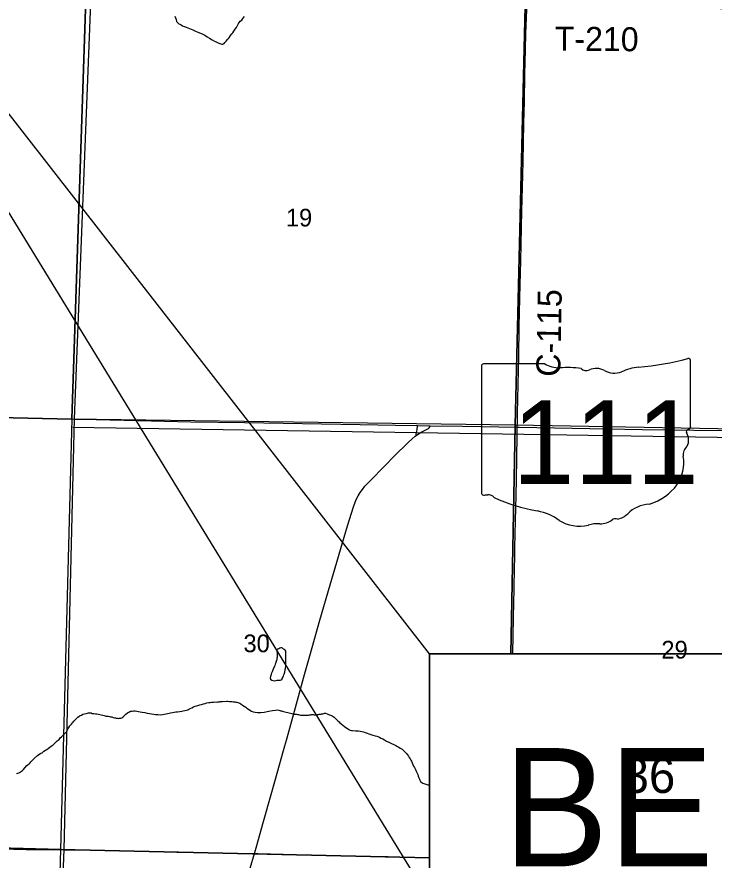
# Model space of a CAD drawing. Extents: x 2.4 to 73.1, y 4.5 to 25.6.
# Drawn here: x 30.38 to 31.205, y 19.109 to 20.107 of the extents above; entities that cross this region are included whole.
import ezdxf

# ---------------------------------------------------------------- set-up
doc = ezdxf.new("R2010")
doc.units = 0
for name, color, linetype in [('GM_X_County_Road', 7, 'Continuous'), ('GM_X_County_Road_Text', 7, 'Continuous'), ('GM_X_Interchange_Ramps', 7, 'Continuous'), ('GM_X_Minor_Lake', 7, 'Continuous'), ('GM_X_Minor_River', 7, 'Continuous'), ('GM_X_Section', 7, 'Continuous'), ('GM_X_Section_Text', 7, 'Continuous'), ('GM_X_State_Location', 7, 'Continuous'), ('GM_X_State_Route', 7, 'Continuous'), ('GM_X_State_Shield', 7, 'Continuous'), ('GM_X_Township', 7, 'Continuous'), ('GM_X_Township_Road', 7, 'Continuous'), ('GM_X_Township_Road_Text', 7, 'Continuous'), ('SH_Text', 7, 'Continuous')]:
    doc.layers.add(name, color=color, linetype=linetype)

msp = doc.modelspace()

# ---------------------------------------------------------------- linework, layer by layer
at = {"layer": 'GM_X_County_Road'}
for points in [[(30.97184, 19.62114), (30.972, 19.6277), (30.97223, 19.63767), (30.97251, 19.65477), (30.97354, 19.70449), (30.97424, 19.74024), (30.9753, 19.78996), (30.9759, 19.81793), (30.97738, 19.87698), (30.97806, 19.90495), (30.97877, 19.93447), (30.97975, 19.98109), (30.98037, 20.00595), (30.98101, 20.03858), (30.98161, 20.06811), (30.982, 20.08676), (30.98299, 20.11472), (30.98303, 20.11613)], [(30.8523, 19.61114), (30.85241, 19.61306), (30.85267, 19.61477), (30.85302, 19.61636), (30.85334, 19.61789), (30.85355, 19.61945), (30.85367, 19.6214), (30.85378, 19.62303)], [(30.8523, 19.61114), (30.85495, 19.61301), (30.85897, 19.61543), (30.8645, 19.61832), (30.86697, 19.61957), (30.86739, 19.61993), (30.86774, 19.62045), (30.86821, 19.6216), (30.8687, 19.6228)], [(30.8687, 19.6228), (30.90718, 19.62221), (30.97184, 19.62114)], [(30.66079, 19.11661), (30.66353, 19.12625), (30.67062, 19.1517), (30.68123, 19.18907), (30.68755, 19.21151), (30.69513, 19.23844), (30.69938, 19.25338), (30.71072, 19.29377), (30.72015, 19.32824), (30.72643, 19.3507), (30.73819, 19.39259), (30.7503, 19.43439), (30.77095, 19.50445), (30.77796, 19.52669), (30.77949, 19.53112), (30.7813, 19.53545), (30.78345, 19.53963), (30.78589, 19.54363), (30.78858, 19.54747), (30.79155, 19.5511), (30.79683, 19.55683), (30.81537, 19.57566), (30.82626, 19.58676), (30.84288, 19.60311), (30.84749, 19.60733), (30.85112, 19.61029), (30.8523, 19.61114)], [(30.53426, 18.61669), (30.53823, 18.63398), (30.54275, 18.65366), (30.55594, 18.71123), (30.56416, 18.74761), (30.57122, 18.77783), (30.57467, 18.79297), (30.58178, 18.82482), (30.58938, 18.85816), (30.59633, 18.88686), (30.60225, 18.90941), (30.60874, 18.93342), (30.61552, 18.95734), (30.62147, 18.97827), (30.64194, 19.05), (30.65591, 19.09934), (30.66079, 19.11661)]]:
    msp.add_lwpolyline(points, dxfattribs=at)
at = {"layer": 'GM_X_Interchange_Ramps'}
msp.add_lwpolyline([(30.41612, 18.61875), (30.43582, 19.1212), (30.44784, 19.63098), (30.47252, 20.25413), (30.47626, 20.50995), (30.48376, 20.60471), (30.48414, 20.61558), (30.49896, 21.13416), (30.49917, 21.1385), (30.51254, 21.51156)], dxfattribs=at)
at = {"layer": 'GM_X_Minor_Lake'}
for points in [[(30.68733, 19.35758), (30.68765, 19.3512), (30.68763, 19.35025), (30.6876, 19.34893), (30.68738, 19.3476), (30.68717, 19.34666), (30.68714, 19.34552), (30.68674, 19.34458), (30.68653, 19.34363), (30.68632, 19.34269), (30.68591, 19.34156), (30.68551, 19.34062), (30.68491, 19.33911), (30.6845, 19.33817), (30.6841, 19.33704), (30.68351, 19.33611), (30.68291, 19.33479), (30.68229, 19.3329), (30.68169, 19.33159), (30.68129, 19.33065), (30.68069, 19.32914), (30.68048, 19.3282), (30.68007, 19.32707), (30.67966, 19.32594), (30.67962, 19.32404), (30.67997, 19.32289), (30.68147, 19.32191), (30.68298, 19.3213), (30.68487, 19.32107), (30.68659, 19.32141), (30.68774, 19.32158), (30.68926, 19.32173), (30.69021, 19.32171), (30.69116, 19.32169), (30.69232, 19.32223), (30.69347, 19.32278), (30.69368, 19.32372), (30.69467, 19.3256), (30.69527, 19.32653), (30.69549, 19.32786), (30.69608, 19.32898), (30.6963, 19.33012), (30.6967, 19.33125), (30.69692, 19.33219), (30.69713, 19.33333), (30.69734, 19.33427), (30.69756, 19.33541), (30.69777, 19.33635), (30.69781, 19.33787), (30.69784, 19.33939), (30.69786, 19.34034), (30.6979, 19.34186), (30.69796, 19.3447), (30.69798, 19.34565), (30.698, 19.3466), (30.69803, 19.34774), (30.69806, 19.34907), (30.6979, 19.35021), (30.69812, 19.35154), (30.69814, 19.35249), (30.69798, 19.35382), (30.698, 19.35477), (30.69783, 19.35591), (30.6973, 19.35725), (30.69617, 19.35804), (30.69523, 19.35844), (30.69411, 19.35941), (30.69317, 19.35982), (30.69204, 19.36003), (30.69088, 19.35949), (30.68954, 19.35895), (30.68838, 19.35821), (30.68742, 19.35767), (30.68733, 19.35758)], [(30.68733, 19.35758), (30.68765, 19.3512), (30.68763, 19.35025), (30.6876, 19.34893), (30.68738, 19.3476), (30.68717, 19.34666), (30.68714, 19.34552), (30.68674, 19.34458), (30.68653, 19.34363), (30.68632, 19.34269), (30.68591, 19.34156), (30.68551, 19.34062), (30.68491, 19.33911), (30.6845, 19.33817), (30.6841, 19.33704), (30.68351, 19.33611), (30.68291, 19.33479), (30.68229, 19.3329), (30.68169, 19.33159), (30.68129, 19.33065), (30.68069, 19.32914), (30.68048, 19.3282), (30.68007, 19.32707), (30.67966, 19.32594), (30.67962, 19.32404), (30.67997, 19.32289), (30.68147, 19.32191), (30.68298, 19.3213), (30.68487, 19.32107), (30.68659, 19.32141), (30.68774, 19.32158), (30.68926, 19.32173), (30.69021, 19.32171), (30.69116, 19.32169), (30.69232, 19.32223), (30.69347, 19.32278), (30.69368, 19.32372)], [(30.69368, 19.32372), (30.69467, 19.3256), (30.69527, 19.32653), (30.69549, 19.32786), (30.69608, 19.32898), (30.6963, 19.33012), (30.6967, 19.33125), (30.69692, 19.33219), (30.69713, 19.33333), (30.69734, 19.33427), (30.69756, 19.33541), (30.69777, 19.33635), (30.69781, 19.33787), (30.69784, 19.33939), (30.69786, 19.34034), (30.6979, 19.34186), (30.69796, 19.3447), (30.69798, 19.34565), (30.698, 19.3466), (30.69803, 19.34774), (30.69806, 19.34907), (30.6979, 19.35021), (30.69812, 19.35154), (30.69814, 19.35249), (30.69798, 19.35382), (30.698, 19.35477), (30.69783, 19.35591), (30.6973, 19.35725), (30.69617, 19.35804), (30.69523, 19.35844), (30.69411, 19.35941), (30.69317, 19.35982), (30.69204, 19.36003), (30.69088, 19.35949), (30.68954, 19.35895), (30.68838, 19.35821), (30.68742, 19.35767), (30.68733, 19.35758)]]:
    msp.add_lwpolyline(points, dxfattribs=at)
at = {"layer": 'GM_X_Minor_River'}
for points in [[(30.5668, 20.1074), (30.56732, 20.1053), (30.56804, 20.10338), (30.56874, 20.10109), (30.57023, 20.09953), (30.57134, 20.09837), (30.57247, 20.09777), (30.57397, 20.09698), (30.57566, 20.09599), (30.57755, 20.09519), (30.58, 20.09437), (30.58791, 20.09115), (30.59036, 20.09015), (30.59393, 20.08855), (30.59695, 20.08734), (30.59977, 20.08614), (30.60221, 20.08475), (30.60483, 20.08298), (30.60784, 20.0812), (30.61084, 20.07943), (30.61365, 20.07765), (30.61628, 20.07645), (30.61854, 20.07545), (30.62005, 20.07504), (30.621, 20.07464), (30.62213, 20.07442), (30.62346, 20.0742), (30.625, 20.07512), (30.62597, 20.07623), (30.62734, 20.07772), (30.6289, 20.07959), (30.63007, 20.08089)], [(30.63007, 20.08089), (30.63125, 20.08238), (30.63243, 20.08445), (30.634, 20.08631), (30.63517, 20.0878), (30.63654, 20.08967), (30.63793, 20.09192), (30.63949, 20.09397), (30.64069, 20.09641), (30.64207, 20.09885), (30.64384, 20.10128), (30.64577, 20.10276), (30.64715, 20.10463), (30.6491, 20.10705)], [(32.22285, 19.35283), (32.22507, 19.59303), (30.44608, 19.62066)], [(30.49208, 19.27815), (30.49359, 19.27773), (30.4951, 19.27732), (30.49643, 19.2771), (30.49737, 19.27689), (30.49851, 19.27667), (30.49964, 19.27645), (30.5006, 19.27662), (30.50174, 19.2766), (30.50289, 19.27695), (30.50404, 19.27731), (30.505, 19.27785), (30.50578, 19.27879), (30.50695, 19.28009), (30.5087, 19.28157), (30.51063, 19.28304), (30.51236, 19.28395), (30.51428, 19.28486), (30.51619, 19.2852), (30.51772, 19.28535), (30.51962, 19.28531), (30.52549, 19.28423), (30.52814, 19.28379), (30.53098, 19.28334), (30.53382, 19.28271), (30.53647, 19.28227), (30.53912, 19.28183), (30.54159, 19.28158), (30.54386, 19.28115), (30.5467, 19.2809), (30.54917, 19.28084), (30.55184, 19.28116), (30.55413, 19.28149), (30.55623, 19.28182), (30.55795, 19.28216), (30.55986, 19.28269), (30.56158, 19.28303), (30.56368, 19.28355), (30.56578, 19.28388), (30.56769, 19.28422), (30.56978, 19.28436), (30.57264, 19.28468), (30.57474, 19.28501), (30.57665, 19.28535), (30.57856, 19.28568), (30.58047, 19.28621), (30.582, 19.28656), (30.58335, 19.28729), (30.58489, 19.28801), (30.58662, 19.28911), (30.58854, 19.29002), (30.59085, 19.29091), (30.59372, 19.2918), (30.59621, 19.2925), (30.59831, 19.29302), (30.60061, 19.29373), (30.60271, 19.29425), (30.60462, 19.29478), (30.60673, 19.2953), (30.60863, 19.29545), (30.61015, 19.2956), (30.61129, 19.29558), (30.61244, 19.29574), (30.61377, 19.2959), (30.61548, 19.29586), (30.61701, 19.29602), (30.61834, 19.29618), (30.61948, 19.29615), (30.62044, 19.29632), (30.62158, 19.2963), (30.6231, 19.29645), (30.62824, 19.29671), (30.62938, 19.29669), (30.63128, 19.29665), (30.6328, 19.29642), (30.63432, 19.29639), (30.63602, 19.29616), (30.63754, 19.29593), (30.63886, 19.29571), (30.64, 19.2955), (30.64113, 19.29528), (30.64226, 19.29488), (30.6434, 19.29447), (30.6449, 19.29368), (30.64658, 19.29231), (30.64883, 19.29112), (30.65052, 19.28994), (30.65201, 19.28858), (30.65369, 19.28721), (30.65537, 19.28603), (30.65744, 19.28504), (30.65951, 19.28423), (30.66178, 19.2838), (30.66463, 19.28336), (30.66824, 19.28346), (30.67224, 19.28394), (30.67798, 19.28514), (30.68218, 19.286), (30.68561, 19.2863), (30.68808, 19.28643), (30.6896, 19.28621)], [(30.37934, 19.21119), (30.38068, 19.21154), (30.38183, 19.21189), (30.38299, 19.21263), (30.38395, 19.21317), (30.38511, 19.21391), (30.38627, 19.21483), (30.38743, 19.21594), (30.38919, 19.21818), (30.39134, 19.2206), (30.39328, 19.22227), (30.39482, 19.22299), (30.39541, 19.22393), (30.39639, 19.22505), (30.39737, 19.22635), (30.39833, 19.22709), (30.3995, 19.2282), (30.40009, 19.22914), (30.40397, 19.23266), (30.40551, 19.23358), (30.40648, 19.23431), (30.40821, 19.23522), (30.40956, 19.23576), (30.41169, 19.23761), (30.41362, 19.23871), (30.41535, 19.23981), (30.41709, 19.2411), (30.41883, 19.24239), (30.42038, 19.2435), (30.42135, 19.24442), (30.42231, 19.24497), (30.42348, 19.24589), (30.42503, 19.24757), (30.42639, 19.24868), (30.42756, 19.24979), (30.42872, 19.25071), (30.42969, 19.25164), (30.43106, 19.25332), (30.43261, 19.2548), (30.43398, 19.25629), (30.43533, 19.2574), (30.4365, 19.25851), (30.43748, 19.25963), (30.43844, 19.26037), (30.43885, 19.2615), (30.43926, 19.26263), (30.43985, 19.26375), (30.44044, 19.26469), (30.44123, 19.26581), (30.44241, 19.2675), (30.44319, 19.26843), (30.44417, 19.26973), (30.44534, 19.27123), (30.44632, 19.27216), (30.44729, 19.27327), (30.44885, 19.27495), (30.45196, 19.27791), (30.45332, 19.27902), (30.45467, 19.27994), (30.45601, 19.28048), (30.45793, 19.28139), (30.45985, 19.28191), (30.46157, 19.28244), (30.4631, 19.28279), (30.46443, 19.28295), (30.46539, 19.28312), (30.46653, 19.28309), (30.46747, 19.28288), (30.46879, 19.28247), (30.47069, 19.28224), (30.47258, 19.282), (30.47448, 19.28177), (30.47619, 19.28154), (30.47789, 19.28113), (30.4794, 19.28071), (30.48129, 19.28029), (30.48318, 19.27987), (30.48526, 19.27925), (30.48773, 19.279), (30.48924, 19.27878), (30.49056, 19.27837), (30.49208, 19.27815)], [(30.6896, 19.28621), (30.69073, 19.28599), (30.69167, 19.28559), (30.69281, 19.28538), (30.69394, 19.28497), (30.69527, 19.28475), (30.69678, 19.28434), (30.69829, 19.28392), (30.70037, 19.2835), (30.70207, 19.28289), (30.70358, 19.28266), (30.7049, 19.28225), (30.70623, 19.28204), (30.70736, 19.28163), (30.7085, 19.2816), (30.70964, 19.28139), (30.71059, 19.28137), (30.71172, 19.28115), (30.71305, 19.28093), (30.71551, 19.2805), (30.71722, 19.28046), (30.72273, 19.28033), (30.72464, 19.28048), (30.72616, 19.28063), (30.72749, 19.28079), (30.72845, 19.28096), (30.7294, 19.28094), (30.73035, 19.28092), (30.73149, 19.28089), (30.7332, 19.28085), (30.73434, 19.28083), (30.73548, 19.28099), (30.73663, 19.28116), (30.73758, 19.28132), (30.73854, 19.28149), (30.73968, 19.28166), (30.74063, 19.28183), (30.74178, 19.28199), (30.74292, 19.28215), (30.74388, 19.28251), (30.74502, 19.28249), (30.74691, 19.28206), (30.74861, 19.28127), (30.74974, 19.28086), (30.75087, 19.28045), (30.752, 19.28005), (30.75294, 19.27946), (30.75387, 19.27868), (30.75518, 19.27789), (30.75667, 19.27634), (30.75797, 19.27517), (30.75908, 19.27381), (30.76002, 19.27303), (30.76095, 19.27225), (30.76207, 19.27127), (30.76337, 19.27011), (30.76561, 19.26835), (30.76729, 19.26698), (30.76917, 19.2658), (30.77104, 19.26442), (30.77272, 19.26325), (30.77423, 19.26264), (30.77554, 19.26204), (30.77669, 19.26202), (30.7803, 19.26194), (30.78182, 19.2619), (30.78409, 19.26166), (30.7858, 19.26143), (30.78788, 19.261), (30.78977, 19.26058), (30.79204, 19.25996), (30.79411, 19.25896), (30.79637, 19.25815), (30.79863, 19.25734), (30.80109, 19.25672), (30.80354, 19.2559), (30.80562, 19.25529), (30.80864, 19.25427), (30.81052, 19.25328), (30.81258, 19.25228), (30.81465, 19.25109), (30.81709, 19.24971), (30.81972, 19.24832), (30.82292, 19.24692), (30.82574, 19.24552), (30.82818, 19.24433), (30.83006, 19.24334), (30.83175, 19.24254), (30.83344, 19.24136), (30.83569, 19.23998), (30.83755, 19.23823), (30.83922, 19.23667), (30.84071, 19.23493), (30.842, 19.23338), (30.8431, 19.23165), (30.84402, 19.23011), (30.84513, 19.22875), (30.84585, 19.22722), (30.84677, 19.22568), (30.8473, 19.22396), (30.84839, 19.22184)], [(30.84839, 19.22184), (30.84911, 19.22012), (30.85021, 19.21819), (30.8513, 19.21589), (30.8524, 19.21397), (30.8533, 19.21186), (30.85401, 19.20994), (30.85473, 19.20802), (30.85526, 19.20611), (30.85599, 19.20477), (30.85652, 19.20324), (30.85744, 19.2017), (30.85894, 19.20071), (30.86025, 19.19973), (30.86591, 19.1979), (30.86803, 19.19785)]]:
    msp.add_lwpolyline(points, dxfattribs=at)
at = {"layer": 'GM_X_Section'}
for points in [[(30.46142, 20.1284), (30.4449, 19.63056), (29.94145, 19.64208), (29.95885, 20.13725)], [(30.46148, 20.13105), (30.98121, 20.11878), (30.9693, 19.62349), (30.4449, 19.63056), (30.46142, 20.1284)], [(31.4812, 20.11358), (31.47128, 19.61446), (30.9693, 19.62349), (30.98121, 20.11878)], [(29.94145, 19.64208), (30.4449, 19.63056), (30.43117, 19.12128), (29.92965, 19.13465)], [(30.9642, 19.35283), (30.9693, 19.62349), (30.4449, 19.63056), (30.43117, 19.12128), (30.86803, 19.11145), (30.86803, 19.35283)], [(31.46656, 19.35283), (31.47128, 19.61446), (30.9693, 19.62349), (30.9642, 19.35283)], [(29.92965, 19.13465), (30.43117, 19.12128), (30.41719, 18.61809), (29.91527, 18.62994)], [(30.86803, 19.11145), (30.43117, 19.12128), (30.41719, 18.61809), (30.9167, 18.60894), (30.95137, 18.60852), (30.95403, 18.77027), (30.86803, 18.77027)]]:
    msp.add_lwpolyline(points, close=True, dxfattribs=at)
at = {"layer": 'GM_X_State_Route'}
for points in [[(30.19518, 19.63567), (30.22176, 19.63552), (30.24818, 19.63497), (30.28703, 19.63402), (30.31501, 19.63342), (30.39583, 19.63184), (30.43934, 19.6309), (30.44796, 19.6307)], [(30.44796, 19.6307), (30.47353, 19.63013), (30.52327, 19.62908), (30.58543, 19.62758), (30.64916, 19.62646), (30.78594, 19.62408), (30.82791, 19.62343), (30.85378, 19.62303), (30.8687, 19.6228)], [(30.8687, 19.6228), (30.90718, 19.62221), (30.97184, 19.62114)], [(30.97184, 19.62114), (30.97401, 19.62108), (31.01598, 19.62036), (31.12011, 19.6185), (31.18073, 19.61748), (31.21959, 19.61694)]]:
    msp.add_lwpolyline(points, dxfattribs=at)
at = {"layer": 'GM_X_State_Shield'}
for p, q in [((31.17681, 19.62127), (31.17681, 19.69978)), ((30.92962, 19.69348), (30.92962, 19.54339)), ((31.00444, 19.69607), (30.93205, 19.69607)), ((31.17678, 19.62129), (31.17681, 19.62127))]:
    msp.add_line(p, q, dxfattribs=at)
for centre, major_axis, start_param, end_param in [((30.93245, 19.6938), (0.00286, 0), 1.712693, 3.28349), ((31.02168, 19.71349), (0.02778, 0), 4.042523, 4.731795), ((31.08876, 19.90069), (0.26214, 0), 4.814394, 5.042369), ((31.17407, 19.70011), (0.00275, 0), 6.141152, 7.989035), ((31.03089, 19.6118), (0.09971, 0), 1.404758, 1.657858), ((31.05353, 19.69458), (0.00801, 0), 3.836095, 5.185415), ((31.06529, 19.67723), (0.01666, 0), 0.950623, 2.079405), ((31.0868, 19.70103), (0.02004, 0), 4.081561, 5.145723), ((31.12219, 19.65022), (0.05274, 0), 1.699011, 2.107814), ((31.17617, 19.61551), (0.00426, 0), 1.883978, 3.671073), ((31.17387, 19.62097), (0.00294, 0), 5.05454, 6.418171), ((31.14908, 19.60558), (0.02556, 0), 5.934695, 6.695948), ((31.18667, 19.58841), (0.0186, 0), 2.387724, 3.262537), ((31.10344, 19.57843), (0.06557, 0), 5.101752, 6.440018), ((30.93248, 19.54306), (0.00289, 0), 3.00124, 4.508301), ((30.93292, 19.55842), (0.02205, 0), 4.665946, 4.897461), ((30.93743, 19.53473), (0.00795, 0), 0.519207, 1.627899), ((31.0378, 19.66958), (0.1893, 0), 4.195997, 4.488961), ((31.13109, 19.50126), (0.03591, 0), 1.647645, 2.488434), ((30.98136, 19.47596), (0.05923, 0), 0.823519, 1.323587), ((31.08559, 19.52885), (0.02118, 0), 4.937069, 5.64225), ((31.04542, 19.53399), (0.03758, 0), 4.026481, 4.996735), ((31.06713, 19.4821), (0.03088, 0), 1.495662, 1.94098), ((31.06988, 19.52275), (0.02002, 0), 4.691044, 5.507374), ((31.08799, 19.50821), (0.00564, 0), 1.147584, 2.315152)]:
    msp.add_ellipse(centre, major_axis=major_axis, ratio=0.8, start_param=start_param, end_param=end_param, dxfattribs=at)
at = {"layer": 'GM_X_Township'}
msp.add_lwpolyline([(30.41612, 18.61875), (30.43582, 19.1212), (30.44784, 19.63098), (30.47252, 20.25413), (30.47626, 20.50995), (30.48376, 20.60471), (30.48414, 20.61558), (30.49896, 21.13416), (30.49917, 21.1385), (30.51254, 21.51156)], dxfattribs=at)
at = {"layer": 'GM_X_Township_Road'}
for points in [[(30.9665, 19.35283), (30.96654, 19.3548), (30.96704, 19.37344), (30.9675, 19.39676), (30.96815, 19.42939), (30.96866, 19.45582), (30.96885, 19.46514), (30.96899, 19.47913), (30.97016, 19.52575), (30.97058, 19.53973), (30.97093, 19.55994), (30.97144, 19.58325), (30.97178, 19.61279), (30.97178, 19.61745), (30.97184, 19.62114)], [(30.18067, 19.12692), (30.1835, 19.12642), (30.18588, 19.12621), (30.18834, 19.12607), (30.20309, 19.1258), (30.22633, 19.12508), (30.26042, 19.12439), (30.28676, 19.12376), (30.3162, 19.12302), (30.33945, 19.12263), (30.36114, 19.12202), (30.39059, 19.12152), (30.43594, 19.12093), (30.43642, 19.12093)], [(30.43642, 19.12093), (30.44315, 19.12094), (30.46957, 19.12059), (30.52708, 19.11957), (30.56904, 19.11838), (30.58613, 19.11807), (30.63898, 19.11689), (30.66079, 19.11661)], [(30.66079, 19.11661), (30.6654, 19.11655), (30.69492, 19.11577), (30.71046, 19.11526), (30.726, 19.11501), (30.77418, 19.11393), (30.81925, 19.11299), (30.86803, 19.11158)]]:
    msp.add_lwpolyline(points, dxfattribs=at)
at = {"layer": 'SH_Text'}
for points in [[(30.86803, 19.35283), (30.03412, 20.42327), (30.86803, 19.06155)], [(30.86803, 18.77027), (30.86803, 19.35283), (30.86803, 19.35283), (30.86803, 18.77027)], [(30.86803, 18.77027), (32.37206, 18.77027), (32.37206, 19.35283), (30.86803, 19.35283)]]:
    msp.add_lwpolyline(points, close=True, dxfattribs=at)

# ---------------------------------------------------------------- texts
at = {"layer": 'GM_X_County_Road_Text'}
msp.add_text('C-115', height=0.028409, rotation=88.89812, dxfattribs=at).set_placement((31.02262, 19.68055))
at = {"layer": 'GM_X_Section_Text'}
for s, height, p in [('19', 0.020928, (30.69806, 19.85856)), ('30', 0.020928, (30.64785, 19.35481)), ('29', 0.020928, (31.14243, 19.34732)), ('36', 0.041856, (31.09653, 19.18827))]:
    msp.add_text(s, height=height, rotation=0.00001, dxfattribs=at).set_placement(p)
at = {"layer": 'GM_X_State_Location'}
for s, p in [('s', (31.05045, 19.60848)), ('r', (31.05044, 19.60848))]:
    msp.add_text(s, height=0.0000947, dxfattribs=at).set_placement(p)
msp.add_text('111', height=0.0000947, rotation=0.00001, dxfattribs=at).set_placement((31.01702, 19.60159))
at = {"layer": 'GM_X_State_Shield'}
msp.add_text('111', height=0.098877, dxfattribs=at).set_placement((30.96604, 19.55398))
at = {"layer": 'GM_X_Township_Road_Text'}
msp.add_text('T-210', height=0.028409, rotation=359.4386, dxfattribs=at).set_placement((31.01612, 20.06673))
at = {"layer": 'SH_Text'}
msp.add_text('BEGIN PROJECT', height=0.1399997, rotation=360, dxfattribs=at).set_placement((30.95487, 19.10137))

doc.saveas('drawing.dxf')
